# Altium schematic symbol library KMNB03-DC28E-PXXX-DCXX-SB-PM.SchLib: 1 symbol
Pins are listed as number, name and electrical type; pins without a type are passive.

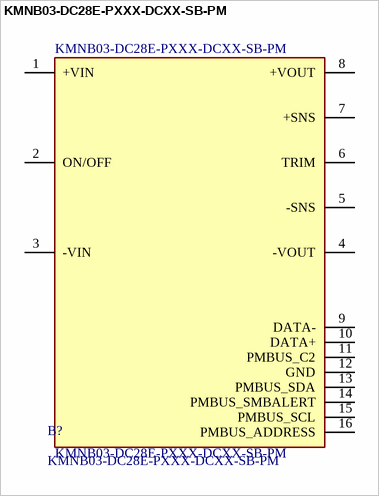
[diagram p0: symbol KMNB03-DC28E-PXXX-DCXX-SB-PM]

## KMNB03-DC28E-PXXX-DCXX-SB-PM
designator B?
9-40Vin XXVout XXXW Nonisolated Sixteenth Brick; MFG: KOLT
footprint KMNB03-DC28E-PXXX-DCXX-SB-PM
pins: 1 +VIN, 2 ON/OFF, 3 -VIN, 4 -VOUT, 5 -SNS, 6 TRIM, 7 +SNS, 8 +VOUT, 9 DATA-, 10 DATA+, 11 PMBUS_C2, 12 GND, 13 PMBUS_SDA, 14 PMBUS_SMBALERT, 15 PMBUS_SCL, 16 PMBUS_ADDRESS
